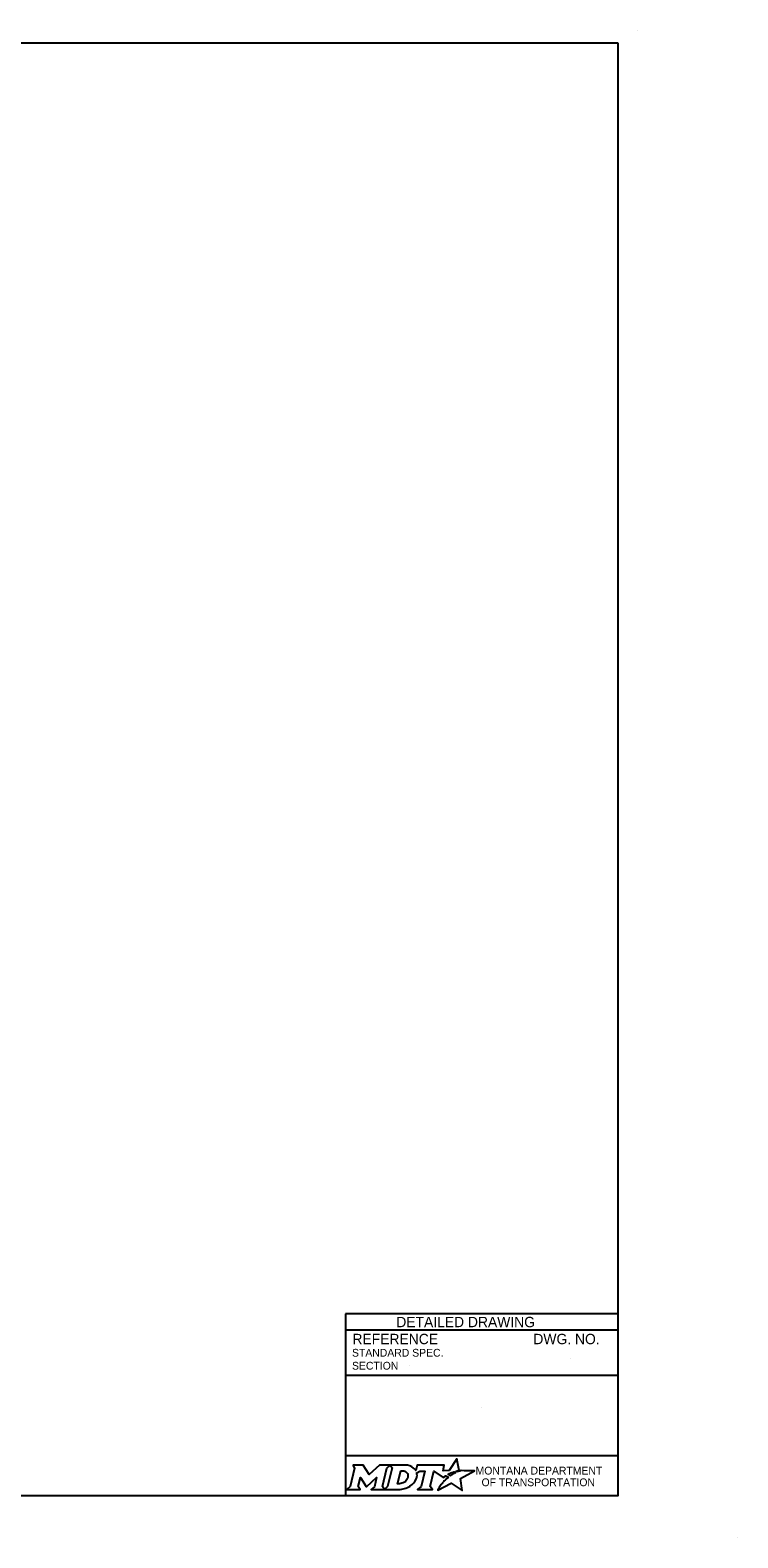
# Model space of a CAD drawing. Extents: x 49991.4 to 50021, y 49987.6 to 50011.4.
# Drawn here: x 50004.09 to 50009.54, y 49999.74 to 50011.36 of the extents above; entities that cross this region are included whole.
import ezdxf

# ---------------------------------------------------------------- set-up
doc = ezdxf.new("R2010")
doc.units = 0
doc.layers.add('Level 1', color=7, linetype='Continuous')
doc.layers.add('Level 2', color=7, linetype='Continuous')

msp = doc.modelspace()

# ---------------------------------------------------------------- linework, layer by layer
at = {"layer": 'Level 1'}
for p, q in [((50008.765, 50011.363), (50008.765, 50011.363)), ((50009.537, 49999.736), (50009.537, 49999.736))]:
    msp.add_line(p, q, dxfattribs=at)
msp.add_lwpolyline([(50008.615, 50011.263), (50000.336, 50011.263), (50000.336, 50000.062), (50008.615, 50000.062)], close=True, dxfattribs=at)
at = {"layer": 'Level 2'}
for p, q in [((50008.615, 50001.462), (50006.515, 50001.462)), ((50006.515, 50001.462), (50006.515, 50000.062)), ((50008.615, 50001.337), (50006.515, 50001.337)), ((50007.009, 50001.063), (50007.009, 50001.063)), ((50008.251, 50001.122), (50008.251, 50001.122)), ((50008.615, 50000.987), (50006.515, 50000.987)), ((50007.565, 50000.738), (50007.565, 50000.738)), ((50008.615, 50000.369), (50006.515, 50000.369))]:
    msp.add_line(p, q, dxfattribs=at)
for points in [[(50007.377, 50000.245), (50007.367, 50000.25), (50007.378, 50000.253), (50007.39, 50000.255), (50007.373, 50000.345), (50007.313, 50000.254), (50007.266, 50000.253), (50007.276, 50000.297), (50007.067, 50000.297), (50007.057, 50000.255), (50007.051, 50000.263)], [(50006.57, 50000.297), (50006.584, 50000.274), (50006.551, 50000.131), (50006.525, 50000.108), (50006.627, 50000.108), (50006.613, 50000.131), (50006.629, 50000.201), (50006.673, 50000.132), (50006.678, 50000.132), (50006.753, 50000.202), (50006.737, 50000.13), (50006.712, 50000.108), (50006.814, 50000.108), (50006.8, 50000.132), (50006.833, 50000.274)], [(50006.833, 50000.274), (50006.859, 50000.297), (50006.776, 50000.297), (50006.697, 50000.224), (50006.652, 50000.297), (50006.57, 50000.297)], [(50006.972, 50000.297), (50006.859, 50000.297), (50006.873, 50000.275), (50006.839, 50000.131), (50006.814, 50000.108), (50006.925, 50000.108)], [(50006.996, 50000.211), (50006.995, 50000.203), (50006.992, 50000.193), (50006.988, 50000.185), (50006.982, 50000.178), (50006.976, 50000.171), (50006.968, 50000.164), (50006.959, 50000.16), (50006.95, 50000.156), (50006.941, 50000.154), (50006.932, 50000.153), (50006.916, 50000.153), (50006.94, 50000.253), (50006.956, 50000.253), (50006.963, 50000.252), (50006.971, 50000.25), (50006.977, 50000.247), (50006.983, 50000.243), (50006.988, 50000.238), (50006.992, 50000.232), (50006.995, 50000.226), (50006.996, 50000.218), (50006.996, 50000.215), (50006.996, 50000.211)], [(50007.064, 50000.238), (50007.088, 50000.251), (50007.125, 50000.251), (50007.097, 50000.131), (50007.069, 50000.108), (50007.185, 50000.108), (50007.168, 50000.131), (50007.196, 50000.251), (50007.268, 50000.2), (50007.289, 50000.215), (50007.309, 50000.204)], [(50007.253, 50000.148), (50007.237, 50000.124), (50007.233, 50000.116), (50007.227, 50000.107), (50007.225, 50000.103), (50007.33, 50000.156), (50007.414, 50000.101), (50007.401, 50000.194), (50007.508, 50000.252), (50007.458, 50000.253), (50007.428, 50000.253), (50007.407, 50000.254), (50007.401, 50000.252), (50007.396, 50000.251), (50007.387, 50000.249), (50007.377, 50000.245)], [(50007.327, 50000.217), (50007.324, 50000.215), (50007.306, 50000.225), (50007.316, 50000.231), (50007.32, 50000.233), (50007.329, 50000.237), (50007.335, 50000.239), (50007.343, 50000.243), (50007.35, 50000.245), (50007.362, 50000.238), (50007.358, 50000.236), (50007.353, 50000.233), (50007.349, 50000.231), (50007.344, 50000.228), (50007.342, 50000.227), (50007.339, 50000.225), (50007.337, 50000.224), (50007.334, 50000.222), (50007.332, 50000.221), (50007.329, 50000.219), (50007.327, 50000.217)], [(50006.97, 50000.116), (50006.979, 50000.118), (50006.992, 50000.124), (50007.012, 50000.135)], [(50007.267, 50000.164), (50007.267, 50000.164)]]:
    msp.add_lwpolyline(points, dxfattribs=at)
for centre, radius, start, end in [((50006.995, 50000.219), 0.0709, 339.5329, 15.8582), ((50006.951, 50000.236), 0.118, 300.9103, 339.1383)]:
    msp.add_arc(centre, radius, start, end, dxfattribs=at)
for centre, major_axis, ratio, start_param, end_param in [((50006.97, 50000.25), (0.0834, -0.0037), 0.568097, 0.61298, 1.570796), ((50007.026, 50000.257), (0.0361, -0.0295), 0.469099, 1.225588, 1.570796), ((50006.925, 50000.257), (0, 0.148), 0.987302, 3.139398, 3.456847), ((50007.26, 50000.156), (-0.00694, -0.00806), 0.008222, 0, 3.137361), ((50007.276, 50000.174), (-0.0098, -0.0102), 0.016458, 3.141593, 6.279097), ((50007.297, 50000.194), (-0.0112, -0.0097), 0.021651, 3.157348, 6.283185)]:
    msp.add_ellipse(centre, major_axis=major_axis, ratio=ratio, start_param=start_param, end_param=end_param, dxfattribs=at)

# ---------------------------------------------------------------- texts
for s, height, p in [('DETAILED DRAWING', 0.0799, (50006.906, 50001.36)), ('REFERENCE', 0.08, (50006.568, 50001.229)), ('DWG. NO.', 0.08, (50007.962, 50001.229)), ('STANDARD SPEC.', 0.06, (50006.565, 50001.133)), ('SECTION', 0.06, (50006.565, 50001.033))]:
    msp.add_text(s, height=height, dxfattribs=at).set_placement(p)
for s, p in [('MONTANA DEPARTMENT', (50007.517, 50000.224)), ('OF TRANSPORTATION', (50007.563, 50000.134))]:
    msp.add_text(s, height=0.06, rotation=360, dxfattribs=at).set_placement(p)

doc.saveas('drawing.dxf')
